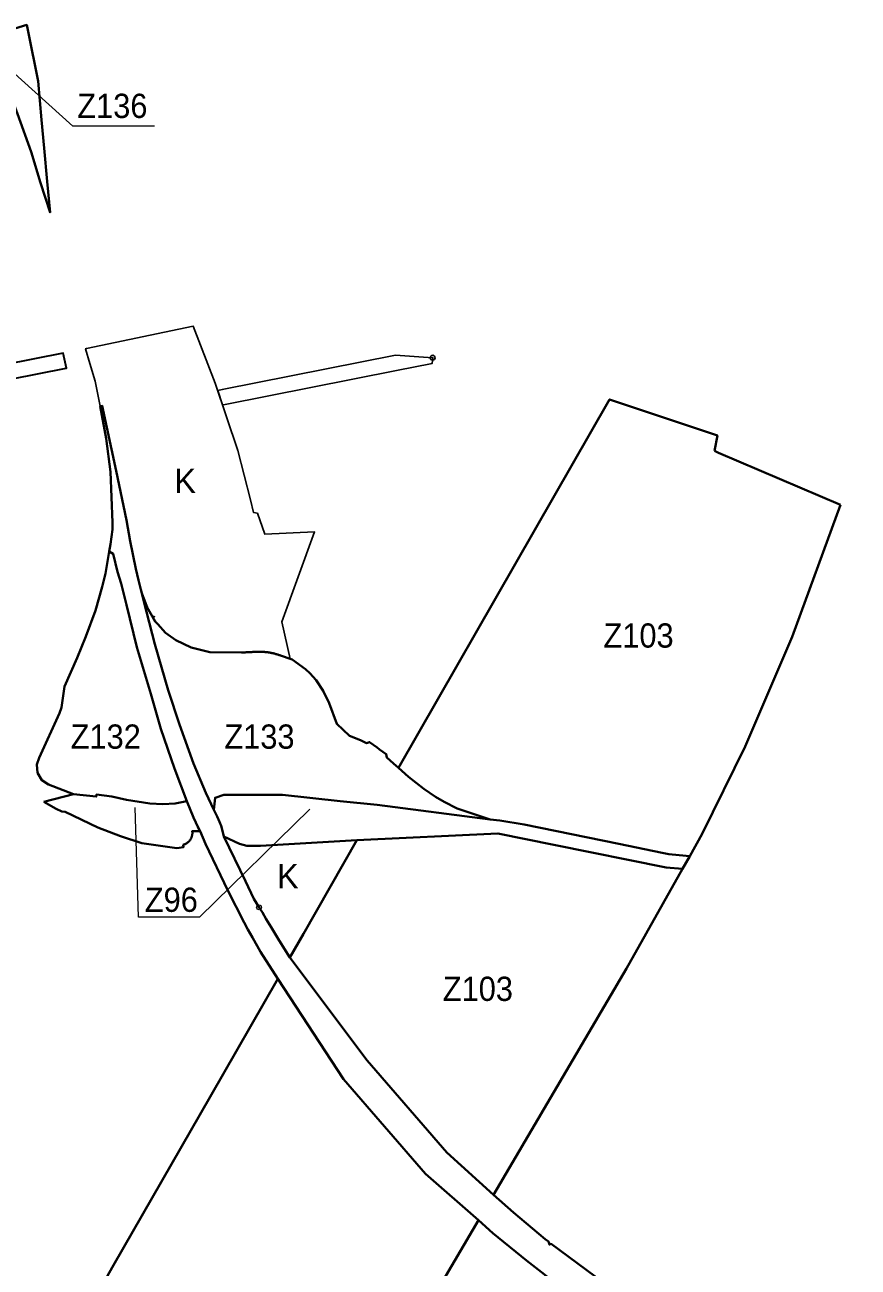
# Model space of a CAD drawing. Extents: x -650276 to -642489, y -1074425 to -1066658.
# Drawn here: x -647869 to -647044, y -1068186 to -1066956 of the extents above; entities that cross this region are included whole.
import ezdxf

# ---------------------------------------------------------------- set-up
doc = ezdxf.new("R2010")
doc.units = 0
doc.header["$LTSCALE"] = 9.6
doc.header["$PDMODE"] = 32
doc.header["$PDSIZE"] = 4.8
for name, color, linetype, lineweight in [('24', 7, 'Continuous', 35), ('4', 7, 'Continuous', 40), ('41', 7, 'Continuous', 25), ('43', 7, 'Continuous', 13), ('44', 7, 'Continuous', 40), ('47', 7, 'Continuous', 13), ('48', 7, 'Continuous', 35)]:
    doc.layers.add(name, color=color, linetype=linetype, lineweight=lineweight)

msp = doc.modelspace()

# ---------------------------------------------------------------- linework, layer by layer
at = {"layer": '24'}
for points in [[(-647708.71, -1067723.99), (-647721.05, -1067691.73), (-647734.63, -1067652.57), (-647744.61, -1067617.96), (-647758.25, -1067571.79), (-647768.5, -1067529.75), (-647773.96, -1067508.48), (-647777.55, -1067496.95), (-647781.85, -1067479.19), (-647785.64, -1067477.02), (-647789.39, -1067498.84), (-647792.54, -1067511.85), (-647799.39, -1067535.48)], [(-647739.417, -1067547.032), (-647740.122, -1067546.264), (-647744.43, -1067538.658), (-647751.41, -1067526.58), (-647740.49, -1067568.67), (-647727.37, -1067614.33), (-647715.92, -1067648.12), (-647702.04, -1067686.86)], [(-647799.39, -1067535.48), (-647808.71, -1067561.03), (-647817.59, -1067582.4)], [(-647737.867, -1067548.624), (-647738.189, -1067548.293), (-647739.417, -1067547.032)], [(-647650.7, -1067576.803), (-647651.205, -1067576.828), (-647651.711, -1067576.853), (-647651.965, -1067576.865), (-647654.743, -1067576.996), (-647685.968, -1067576.68), (-647704.458, -1067572.034), (-647719.661, -1067564.884), (-647729.802, -1067557.462), (-647737.581, -1067548.996), (-647737.867, -1067548.624)], [(-647647.666, -1067576.65), (-647647.897, -1067576.661), (-647648.172, -1067576.675), (-647648.677, -1067576.701), (-647649.183, -1067576.727), (-647649.689, -1067576.752), (-647650.194, -1067576.778), (-647650.7, -1067576.803)], [(-647646.149, -1067576.572), (-647646.655, -1067576.598), (-647647.161, -1067576.624), (-647647.666, -1067576.65)], [(-647644.899, -1067576.509), (-647645.138, -1067576.521), (-647645.644, -1067576.546), (-647646.149, -1067576.572)], [(-647644.127, -1067576.471), (-647644.633, -1067576.496), (-647644.899, -1067576.509)], [(-647639.583, -1067576.291), (-647640.087, -1067576.306), (-647640.592, -1067576.322), (-647641.096, -1067576.34), (-647641.601, -1067576.359), (-647641.901, -1067576.371), (-647642.106, -1067576.38), (-647642.611, -1067576.401), (-647643.117, -1067576.424), (-647643.622, -1067576.447), (-647644.127, -1067576.471)], [(-647638.902, -1067576.275), (-647639.078, -1067576.278), (-647639.583, -1067576.291)], [(-647629.774, -1067576.618), (-647629.896, -1067576.607), (-647630.441, -1067576.585), (-647631.108, -1067576.559), (-647631.775, -1067576.533), (-647632.441, -1067576.507), (-647636.423, -1067576.351), (-647637.067, -1067576.326), (-647637.569, -1067576.307), (-647638.072, -1067576.287), (-647638.574, -1067576.267), (-647638.902, -1067576.275)], [(-647628.441, -1067576.759), (-647629.107, -1067576.685), (-647629.774, -1067576.618)], [(-647621.877, -1067578.106), (-647622.532, -1067577.965), (-647623.213, -1067577.819), (-647623.843, -1067577.683), (-647627.118, -1067576.98), (-647627.775, -1067576.839), (-647628.441, -1067576.759)], [(-647618.023, -1067579.297), (-647618.661, -1067579.083), (-647619.352, -1067578.859), (-647619.942, -1067578.674), (-647620.586, -1067578.478), (-647621.269, -1067578.278), (-647621.877, -1067578.106)], [(-647615.566, -1067580.184), (-647616.12, -1067579.975), (-647616.752, -1067579.743), (-647617.451, -1067579.494), (-647618.023, -1067579.297)], [(-647547.663, -1067659.519), (-647560.187, -1067647.458), (-647567.744, -1067627.24), (-647573.605, -1067614.951), (-647580.539, -1067604.432), (-647586.864, -1067597.411), (-647591.227, -1067593.613), (-647604.415, -1067584.047), (-647606.559, -1067583.309), (-647615.048, -1067580.385), (-647615.566, -1067580.184)], [(-647817.59, -1067582.4), (-647829.97, -1067610.62), (-647832.8, -1067631.53), (-647835.06, -1067637.01), (-647855.24, -1067681.26), (-647857.51, -1067687.74), (-647856.9, -1067695.97)], [(-647499.095, -1067691.163), (-647503.97, -1067686.73), (-647510.6, -1067680.86), (-647511.24, -1067677.53), (-647517.74, -1067672.85), (-647520.13, -1067671.13), (-647527.76, -1067665.65), (-647530.82, -1067666.65), (-647536.83, -1067663.64), (-647547.663, -1067659.519)], [(-647702.04, -1067686.86), (-647690.09, -1067716.05), (-647681.91, -1067732.74), (-647680.804, -1067720.745), (-647672, -1067718), (-647643, -1067718), (-647614, -1067718), (-647557, -1067724), (-647520.145, -1067727.879), (-647408.2, -1067742.37), (-647440.81, -1067731.38), (-647453.87, -1067724.97), (-647462.45, -1067719.84), (-647474.13, -1067711.81), (-647489.3, -1067700.07), (-647499.095, -1067691.163)], [(-647856.9, -1067695.97), (-647852.3, -1067703.36), (-647845.74, -1067707.59), (-647821.02, -1067717.33)], [(-647821.02, -1067717.33), (-647798.5, -1067719.67), (-647798.17, -1067717.58), (-647783.13, -1067719.68), (-647768.53, -1067722.82), (-647745.41, -1067726.6), (-647732.71, -1067727.02), (-647720.45, -1067726.49), (-647708.71, -1067723.99)]]:
    msp.add_lwpolyline(points, dxfattribs=at)
at = {"layer": '4'}
msp.add_lwpolyline([(-647876.57, -1067043.5), (-647863.04, -1067081.36), (-647853.65, -1067111.91), (-647844.3, -1067141.25), (-647847.09, -1067110.58), (-647850.07, -1067077.71), (-647852.63, -1067049.52), (-647856.11, -1067011.21), (-647866.14, -1066961.98), (-647867.46, -1066955.52), (-647905.28, -1066967.07), (-647903.5, -1066972.05)], close=True, dxfattribs=at)
at = {"layer": '4', "lineweight": 13}
msp.add_lwpolyline([(-647740.809, -1067055.795), (-647821.729, -1067055.795), (-647882.822, -1067000.815)], dxfattribs=at)
at = {"layer": '41'}
for p, q in [((-647740.124, -1067546.265), (-647739.417, -1067547.032)), ((-647740, -1067546.181), (-647739.998, -1067546.18)), ((-647640.591, -1067576.33), (-647640.087, -1067576.306))]:
    msp.add_line(p, q, dxfattribs=at)
for points in [[(-647638.68, -1067439.06), (-647642.686, -1067438.46), (-647645.78, -1067425.81), (-647658.13, -1067376.99), (-647680.64, -1067310.37), (-647702.42, -1067253.98), (-647808.25, -1067276.11), (-647809.02, -1067276.27), (-647804.823, -1067290.788)], [(-647465.203, -1067285.115), (-647501.968, -1067282.642), (-647673.685, -1067316.666), (-647678.21, -1067317.562), (-647673.367, -1067331.895), (-647670.77, -1067331.38), (-647501.099, -1067297.762)], [(-647501.099, -1067297.762), (-647465.699, -1067290.747), (-647465.203, -1067285.115)], [(-647804.823, -1067290.788), (-647799.76, -1067308.3), (-647794.54, -1067333.14)], [(-647794.54, -1067333.14), (-647792.52, -1067332.74), (-647778.78, -1067397.1), (-647768.5, -1067446.04)], [(-647615.048, -1067580.385), (-647606.559, -1067583.309), (-647614.75, -1067546.53), (-647582.2, -1067457.65), (-647631.59, -1067459.72), (-647638.68, -1067439.06)], [(-647768.5, -1067446.04), (-647764.89, -1067466.64), (-647759.16, -1067494.01), (-647756.55, -1067505.32), (-647755.255, -1067510.676)], [(-647755.255, -1067510.676), (-647755.159, -1067511.027), (-647754.116, -1067514.604)], [(-647754.116, -1067514.604), (-647753.006, -1067518.156), (-647751.818, -1067521.68), (-647750.545, -1067525.169), (-647749.178, -1067528.619), (-647747.708, -1067532.022), (-647746.127, -1067535.371), (-647744.43, -1067538.658), (-647740.122, -1067546.264)], [(-647742.158, -1067541.404), (-647741.902, -1067541.247), (-647741.647, -1067541.09), (-647740.804, -1067541.512), (-647742.167, -1067542.348)], [(-647739.998, -1067546.18), (-647742.045, -1067542.565), (-647742.167, -1067542.348), (-647742.158, -1067541.404)], [(-647742.167, -1067542.348), (-647742.037, -1067542.56), (-647741.936, -1067542.723), (-647741.743, -1067543.03), (-647741.67, -1067543.146), (-647741.447, -1067543.497), (-647741.402, -1067543.568), (-647741.148, -1067543.963), (-647741.132, -1067543.989), (-647740.859, -1067544.408), (-647740.846, -1067544.427), (-647740.583, -1067544.825), (-647740.541, -1067544.889), (-647740.519, -1067544.919), (-647740.333, -1067545.195), (-647740.265, -1067545.295), (-647740.068, -1067545.582), (-647739.971, -1067545.724), (-647739.801, -1067545.968), (-647739.674, -1067546.15), (-647739.532, -1067546.353), (-647739.504, -1067546.391), (-647739.374, -1067546.575), (-647739.26, -1067546.736), (-647739.072, -1067546.998), (-647738.986, -1067547.117), (-647738.767, -1067547.418), (-647738.709, -1067547.496), (-647738.456, -1067547.839), (-647738.431, -1067547.874), (-647738.148, -1067548.252), (-647737.867, -1067548.624), (-647737.834, -1067548.667), (-647737.581, -1067548.996), (-647737.518, -1067549.078)], [(-647739.966, -1067546.23), (-647739.968, -1067546.231), (-647739.983, -1067546.206)], [(-647737.525, -1067549.085), (-647729.802, -1067557.462), (-647719.661, -1067564.884), (-647704.458, -1067572.034), (-647685.968, -1067576.68)], [(-647685.968, -1067576.68), (-647654.743, -1067576.996), (-647651.965, -1067576.865)], [(-647651.965, -1067576.865), (-647651.711, -1067576.853), (-647651.205, -1067576.828), (-647650.7, -1067576.803), (-647650.194, -1067576.778), (-647649.689, -1067576.752), (-647649.183, -1067576.727), (-647648.677, -1067576.701), (-647648.172, -1067576.675), (-647647.897, -1067576.661), (-647647.666, -1067576.65), (-647647.161, -1067576.624), (-647646.655, -1067576.598), (-647646.149, -1067576.572), (-647645.644, -1067576.546), (-647645.138, -1067576.521), (-647644.899, -1067576.509), (-647644.633, -1067576.496), (-647644.127, -1067576.471), (-647643.622, -1067576.447), (-647643.117, -1067576.424), (-647642.611, -1067576.401), (-647642.106, -1067576.38), (-647641.901, -1067576.371), (-647641.601, -1067576.359), (-647641.096, -1067576.34), (-647640.592, -1067576.322)], [(-647640.087, -1067576.306), (-647639.583, -1067576.291), (-647639.078, -1067576.278), (-647638.902, -1067576.275), (-647638.574, -1067576.267), (-647638.071, -1067576.258), (-647637.567, -1067576.251), (-647637.064, -1067576.246), (-647637.01, -1067576.246), (-647636.419, -1067576.254), (-647635.902, -1067576.265), (-647635.757, -1067576.268), (-647635.094, -1067576.286), (-647635.037, -1067576.288), (-647634.431, -1067576.309), (-647633.767, -1067576.337), (-647633.102, -1067576.37), (-647633.058, -1067576.372), (-647632.9, -1067576.382), (-647632.437, -1067576.408), (-647631.772, -1067576.452), (-647631.106, -1067576.502), (-647631.076, -1067576.504), (-647630.44, -1067576.557), (-647629.896, -1067576.607), (-647629.774, -1067576.618), (-647629.107, -1067576.685), (-647629.091, -1067576.687), (-647628.441, -1067576.759), (-647627.775, -1067576.839), (-647627.107, -1067576.926), (-647626.443, -1067577.019), (-647625.783, -1067577.139), (-647625.14, -1067577.282), (-647625.129, -1067577.284), (-647624.476, -1067577.436), (-647623.824, -1067577.594), (-647623.199, -1067577.752), (-647623.174, -1067577.759), (-647622.525, -1067577.929), (-647621.877, -1067578.106), (-647621.269, -1067578.278), (-647621.23, -1067578.289), (-647620.586, -1067578.478), (-647619.942, -1067578.674), (-647619.352, -1067578.859), (-647619.301, -1067578.875), (-647618.661, -1067579.083), (-647618.023, -1067579.297), (-647617.451, -1067579.494), (-647617.387, -1067579.517), (-647616.752, -1067579.743), (-647616.12, -1067579.975), (-647615.566, -1067580.184), (-647615.489, -1067580.214), (-647615.048, -1067580.385)]]:
    msp.add_lwpolyline(points, dxfattribs=at)
for start, end in [(214.04927, 214.0695), (214.08975, 214.75472)]:
    msp.add_arc((-647670.608, -1067499.289), 83.75, start, end, dxfattribs=at)
msp.add_point((-647465.203, -1067285.115), dxfattribs=at)
at = {"layer": '44'}
for p, q in [((-647489.3, -1067700.07), (-647474.13, -1067711.81)), ((-647540.208, -1067762.876), (-647400.63, -1067756.19))]:
    msp.add_line(p, q, dxfattribs=at)
for points in [[(-647606.818, -1067879.061), (-647617.25, -1067861.95), (-647625.37, -1067848.86), (-647630.3, -1067841.02), (-647633.69, -1067834.31), (-647637.21, -1067829.29), (-647642.29, -1067820.76), (-647650.8, -1067803.28), (-647672.05, -1067758.98), (-647673.47, -1067753.48), (-647673.47, -1067753.48), (-647674.67, -1067748.73), (-647676.47, -1067744.5), (-647678.66, -1067739.38), (-647681.91, -1067732.74), (-647690.09, -1067716.05), (-647702.04, -1067686.86), (-647715.92, -1067648.12), (-647727.37, -1067614.33), (-647740.49, -1067568.67), (-647751.41, -1067526.58), (-647756.55, -1067505.32), (-647759.16, -1067494.01), (-647764.89, -1067466.64), (-647768.5, -1067446.04), (-647778.78, -1067397.1), (-647792.52, -1067332.74), (-647794.54, -1067333.14), (-647788.77, -1067365.03), (-647784.55, -1067398.01), (-647782.39, -1067448.34), (-647782.5, -1067455.11), (-647784.36, -1067469.6), (-647785.64, -1067477.02), (-647781.85, -1067479.19), (-647777.55, -1067496.95), (-647773.96, -1067508.48), (-647768.5, -1067529.75), (-647758.25, -1067571.79), (-647744.61, -1067617.96), (-647734.63, -1067652.57), (-647721.05, -1067691.73), (-647708.71, -1067723.99), (-647702.21, -1067740.43), (-647699.89, -1067745.24), (-647697.85, -1067749.46), (-647695.71, -1067753.9), (-647690.19, -1067766.37), (-647668.13, -1067812.76), (-647651.94, -1067844.36), (-647648.33, -1067851.17), (-647643.83, -1067859.13), (-647635.77, -1067873.43), (-647618.773, -1067899.914)], [(-647185.93, -1067377.38), (-647183.09, -1067362.16), (-647289.924, -1067326.309), (-647364.024, -1067455.561), (-647499.095, -1067691.163), (-647489.3, -1067700.07)], [(-647061.252, -1067430.908), (-647181.878, -1067379.12), (-647185.93, -1067377.38)], [(-647155.592, -1067670.17), (-647108.971, -1067561.55), (-647061.252, -1067430.908)], [(-647708.71, -1067723.99), (-647721.05, -1067691.73), (-647734.63, -1067652.57), (-647744.61, -1067617.96), (-647758.25, -1067571.79), (-647768.5, -1067529.75), (-647773.96, -1067508.48), (-647777.55, -1067496.95), (-647781.85, -1067479.19), (-647785.64, -1067477.02), (-647789.39, -1067498.84), (-647792.54, -1067511.85), (-647799.39, -1067535.48)], [(-647739.417, -1067547.032), (-647740.122, -1067546.264), (-647744.43, -1067538.658), (-647751.41, -1067526.58), (-647740.49, -1067568.67), (-647727.37, -1067614.33), (-647715.92, -1067648.12)], [(-647799.39, -1067535.48), (-647808.71, -1067561.03), (-647817.59, -1067582.4)], [(-647737.867, -1067548.624), (-647738.148, -1067548.252), (-647738.514, -1067547.9), (-647739.417, -1067547.032)], [(-647650.7, -1067576.803), (-647651.205, -1067576.828), (-647651.711, -1067576.853), (-647651.965, -1067576.865), (-647654.743, -1067576.996), (-647685.968, -1067576.68), (-647704.458, -1067572.034), (-647719.661, -1067564.884), (-647729.802, -1067557.462), (-647737.581, -1067548.996), (-647737.867, -1067548.624)], [(-647647.161, -1067576.624), (-647647.666, -1067576.65), (-647647.897, -1067576.661), (-647648.172, -1067576.675), (-647648.677, -1067576.701), (-647649.183, -1067576.727), (-647649.689, -1067576.752), (-647650.194, -1067576.778), (-647650.7, -1067576.803)], [(-647646.149, -1067576.572), (-647646.655, -1067576.598), (-647647.161, -1067576.624)], [(-647644.633, -1067576.496), (-647644.899, -1067576.509), (-647645.138, -1067576.521), (-647645.644, -1067576.546), (-647646.149, -1067576.572)], [(-647643.117, -1067576.424), (-647643.622, -1067576.447), (-647644.127, -1067576.471), (-647644.633, -1067576.496)], [(-647640.592, -1067576.322), (-647641.096, -1067576.34), (-647641.601, -1067576.359), (-647641.901, -1067576.371), (-647642.106, -1067576.38), (-647642.611, -1067576.401), (-647643.117, -1067576.424)], [(-647639.583, -1067576.291), (-647640.087, -1067576.306), (-647640.592, -1067576.322)], [(-647638.902, -1067576.275), (-647639.078, -1067576.278), (-647639.583, -1067576.291)], [(-647632.437, -1067576.408), (-647632.9, -1067576.39), (-647633.102, -1067576.383), (-647633.767, -1067576.357), (-647634.431, -1067576.331), (-647635.095, -1067576.305), (-647635.757, -1067576.28), (-647635.902, -1067576.274), (-647636.419, -1067576.254), (-647637.064, -1067576.246), (-647637.567, -1067576.251), (-647638.071, -1067576.258), (-647638.574, -1067576.267), (-647638.902, -1067576.275)], [(-647629.774, -1067576.618), (-647629.896, -1067576.607), (-647630.44, -1067576.557), (-647631.106, -1067576.502), (-647631.772, -1067576.452), (-647632.437, -1067576.408)], [(-647628.441, -1067576.759), (-647629.107, -1067576.685), (-647629.774, -1067576.618)], [(-647623.199, -1067577.752), (-647623.824, -1067577.594), (-647624.481, -1067577.461), (-647625.149, -1067577.324), (-647625.794, -1067577.193), (-647626.451, -1067577.059), (-647627.107, -1067576.926), (-647627.775, -1067576.839), (-647628.441, -1067576.759)], [(-647621.269, -1067578.278), (-647621.877, -1067578.106), (-647622.525, -1067577.929), (-647623.199, -1067577.752)], [(-647619.352, -1067578.859), (-647619.942, -1067578.674), (-647620.586, -1067578.478), (-647621.269, -1067578.278)], [(-647615.048, -1067580.385), (-647615.566, -1067580.184), (-647616.12, -1067579.975), (-647616.752, -1067579.743), (-647617.451, -1067579.494), (-647618.023, -1067579.297), (-647618.661, -1067579.083), (-647619.352, -1067578.859)], [(-647547.663, -1067659.519), (-647560.187, -1067647.458), (-647567.744, -1067627.24), (-647573.605, -1067614.951), (-647580.539, -1067604.432), (-647586.864, -1067597.411), (-647591.227, -1067593.613), (-647604.415, -1067584.047), (-647606.559, -1067583.309), (-647615.048, -1067580.385)], [(-647817.59, -1067582.4), (-647829.97, -1067610.62), (-647832.8, -1067631.53), (-647835.06, -1067637.01), (-647855.24, -1067681.26), (-647857.51, -1067687.74), (-647856.9, -1067695.97)], [(-647715.92, -1067648.12), (-647702.04, -1067686.86), (-647690.09, -1067716.05), (-647681.91, -1067732.74), (-647680.804, -1067720.745), (-647672, -1067718), (-647643, -1067718), (-647614, -1067718), (-647557, -1067724), (-647520.145, -1067727.879), (-647408.2, -1067742.37), (-647440.81, -1067731.38), (-647453.87, -1067724.97), (-647462.45, -1067719.84), (-647474.13, -1067711.81), (-647489.3, -1067700.07), (-647499.095, -1067691.163)], [(-647499.095, -1067691.163), (-647503.97, -1067686.73), (-647510.6, -1067680.86), (-647511.24, -1067677.53), (-647517.74, -1067672.85), (-647520.13, -1067671.13), (-647527.76, -1067665.65), (-647530.82, -1067666.65), (-647536.83, -1067663.64), (-647547.663, -1067659.519)], [(-647210.537, -1067778.594), (-647198.088, -1067756.5), (-647155.592, -1067670.17)], [(-647856.9, -1067695.97), (-647852.3, -1067703.36), (-647845.74, -1067707.59), (-647821.02, -1067717.33)], [(-647474.13, -1067711.81), (-647462.45, -1067719.84), (-647453.87, -1067724.97), (-647440.81, -1067731.38), (-647408.2, -1067742.37), (-647398.74, -1067743.15)], [(-647695.797, -1067753.719), (-647697.85, -1067749.46), (-647699.89, -1067745.24), (-647702.21, -1067740.43), (-647708.71, -1067723.99), (-647720.45, -1067726.49), (-647732.71, -1067727.02), (-647745.41, -1067726.6), (-647768.53, -1067722.82), (-647783.13, -1067719.68), (-647798.17, -1067717.58), (-647798.5, -1067719.67), (-647821.02, -1067717.33), (-647850.45, -1067724.77)], [(-647850.45, -1067724.77), (-647838.18, -1067731.62), (-647832.56, -1067734.22), (-647829.49, -1067734.58), (-647796.87, -1067750.25), (-647774.54, -1067758.68), (-647753.53, -1067765.58), (-647718.54, -1067770.6), (-647712.01, -1067769.63), (-647712.26, -1067767.28)], [(-647821.02, -1067717.33), (-647798.5, -1067719.67), (-647798.17, -1067717.58), (-647783.13, -1067719.68), (-647768.53, -1067722.82), (-647745.41, -1067726.6), (-647732.71, -1067727.02), (-647720.45, -1067726.49), (-647708.71, -1067723.99)], [(-647520.145, -1067727.879), (-647557, -1067724), (-647614, -1067718), (-647643, -1067718), (-647672, -1067718), (-647680.804, -1067720.745), (-647681.91, -1067732.74)], [(-647398.74, -1067743.15), (-647408.2, -1067742.37), (-647520.145, -1067727.879)], [(-647681.91, -1067732.74), (-647678.66, -1067739.38), (-647676.47, -1067744.5), (-647674.67, -1067748.73), (-647673.47, -1067753.48)], [(-647210.537, -1067778.594), (-647213.92, -1067778.26), (-647231.17, -1067776.55), (-647237.91, -1067775.18), (-647280.78, -1067766.44), (-647374.55, -1067747.34), (-647398.74, -1067743.15)], [(-647398.74, -1067743.15), (-647374.55, -1067747.34), (-647280.78, -1067766.44), (-647237.91, -1067775.18), (-647231.17, -1067776.55), (-647213.92, -1067778.26), (-647210.537, -1067778.594)], [(-647712.26, -1067767.28), (-647711.773, -1067767.135), (-647711.286, -1067766.968), (-647710.799, -1067766.777), (-647710.315, -1067766.562), (-647709.834, -1067766.324), (-647709.359, -1067766.062), (-647708.892, -1067765.776), (-647708.433, -1067765.466), (-647707.985, -1067765.133), (-647707.55, -1067764.777), (-647707.128, -1067764.398), (-647706.723, -1067763.999), (-647706.335, -1067763.579), (-647705.966, -1067763.14), (-647705.617, -1067762.683), (-647705.29, -1067762.21), (-647704.985, -1067761.721), (-647704.704, -1067761.22), (-647704.447, -1067760.707), (-647704.216, -1067760.184), (-647704.01, -1067759.653), (-647703.83, -1067759.117), (-647703.675, -1067758.576), (-647703.547, -1067758.033), (-647703.445, -1067757.489), (-647703.368, -1067756.946), (-647703.315, -1067756.406), (-647703.287, -1067755.87), (-647703.282, -1067755.341), (-647703.3, -1067754.818), (-647703.34, -1067754.304), (-647703.4, -1067753.8), (-647695.797, -1067753.719)], [(-647673.47, -1067753.48), (-647672.05, -1067758.98), (-647672.05, -1067758.98), (-647656.469, -1067766.309), (-647649.22, -1067768.38), (-647635.758, -1067768.38), (-647540.208, -1067762.876)], [(-647540.208, -1067762.876), (-647593.267, -1067855.425), (-647606.818, -1067879.061)], [(-647217.611, -1067791.149), (-647233.83, -1067789.69), (-647345.11, -1067767.28), (-647400.63, -1067756.19), (-647540.208, -1067762.876)], [(-647400.63, -1067756.19), (-647345.11, -1067767.28), (-647233.83, -1067789.69), (-647217.611, -1067791.149), (-647210.537, -1067778.594)], [(-647405.026, -1068113.904), (-647273.297, -1067889.981), (-647217.611, -1067791.149)], [(-647405.026, -1068113.904), (-647451.024, -1068071.886), (-647530.038, -1067980.839), (-647606.818, -1067879.061)], [(-647606.818, -1067879.061), (-647530.038, -1067980.839), (-647451.024, -1068071.886), (-647405.026, -1068113.904)], [(-647618.773, -1067899.914), (-647685.819, -1068016.861), (-647781.346, -1068183.485), (-647791.669, -1068201.583)], [(-647781.204, -1068756.329), (-647675.054, -1068572.919), (-647461.188, -1068209.373), (-647419.713, -1068138.871), (-647472.338, -1068093.096), (-647553.628, -1067999.427), (-647618.773, -1067899.915), (-647618.773, -1067899.914)], [(-647618.773, -1067899.914), (-647553.628, -1067999.427), (-647472.338, -1068093.096), (-647419.713, -1068138.871)], [(-647040.77, -1068349.4), (-647044.93, -1068347.08), (-647053.75, -1068342.11), (-647099.2, -1068318.27), (-647112.813, -1068310.564), (-647142.41, -1068293.81), (-647186.26, -1068269.45), (-647243.39, -1068235.26), (-647246.8, -1068233.08), (-647295.47, -1068201.09), (-647347.74, -1068162.54), (-647349.59, -1068163.24), (-647350.6, -1068160.26), (-647353.81, -1068157.67), (-647385.13, -1068131.51), (-647405.026, -1068113.904)], [(-647419.713, -1068138.871), (-647405.71, -1068151.74), (-647372.38, -1068179.01), (-647337.74, -1068205.67), (-647334.62, -1068208.02), (-647307.39, -1068227.44), (-647281.64, -1068244.34), (-647234.11, -1068273.04), (-647230.83, -1068274.93), (-647174.56, -1068306.35), (-647142.788, -1068322.462), (-647130.29, -1068328.8), (-647079.16, -1068357.01), (-647032.91, -1068382.51), (-647029.23, -1068384.46), (-646997.06, -1068401.37), (-646929.56, -1068435.42), (-646927.06, -1068436.66)]]:
    msp.add_lwpolyline(points, dxfattribs=at)
at = {"layer": '44', "lineweight": 13}
msp.add_lwpolyline([(-647586.774, -1067732.166), (-647696.17, -1067839.096), (-647756.708, -1067839.096), (-647760.132, -1067730.33)], dxfattribs=at)
at = {"layer": '47'}
msp.add_lwpolyline([(-647606.818, -1067879.061), (-647540.208, -1067762.876), (-647635.758, -1067768.38), (-647649.22, -1067768.38), (-647656.469, -1067766.309), (-647672.05, -1067758.98), (-647650.8, -1067803.28), (-647642.29, -1067820.76), (-647637.21, -1067829.29), (-647633.69, -1067834.31), (-647630.3, -1067841.02), (-647625.37, -1067848.86), (-647617.25, -1067861.95)], close=True, dxfattribs=at)
msp.add_point((-647637.21, -1067829.29), dxfattribs=at)
at = {"layer": '48'}
msp.add_lwpolyline([(-647882.66, -1067529.231), (-647926.759, -1067358.379), (-647937.355, -1067316.774), (-647828.376, -1067295.406), (-647828.104, -1067295.352), (-647831.28, -1067280.69), (-647948.488, -1067303.671)], dxfattribs=at)

# ---------------------------------------------------------------- texts
at = {"layer": '4', "width": 0.95}
msp.add_text('Z136', height=24, dxfattribs=at).set_placement((-647817.317, -1067047.713))
at = {"layer": '43'}
for p in [(-647721.126, -1067419.035), (-647619.44, -1067810.434)]:
    msp.add_text('K', height=24, dxfattribs=at).set_placement(p)
at = {"layer": '44', "width": 0.95}
for s, p in [('Z103', (-647295.975, -1067572.121)), ('Z103', (-647295.975, -1067572.121)), ('Z132', (-647823.879, -1067672.215)), ('Z133', (-647671.579, -1067672.215)), ('Z96', (-647750.408, -1067833.749)), ('Z103', (-647455.179, -1067921.933)), ('Z103', (-647455.179, -1067921.933))]:
    msp.add_text(s, height=24, dxfattribs=at).set_placement(p)

doc.saveas('drawing.dxf')
